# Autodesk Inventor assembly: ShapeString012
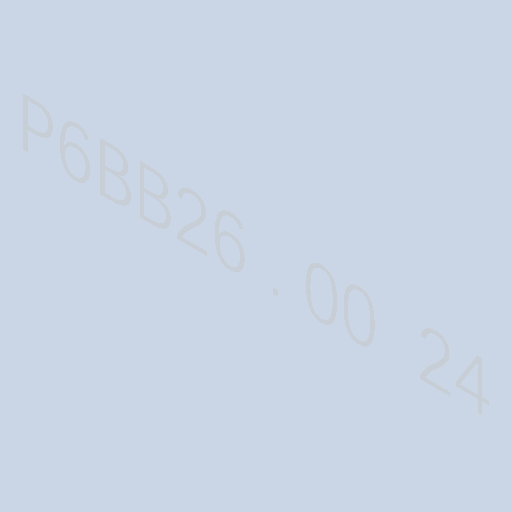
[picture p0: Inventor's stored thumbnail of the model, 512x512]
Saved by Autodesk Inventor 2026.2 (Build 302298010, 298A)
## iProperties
Created: 2026-10
Part Number: ShapeString012
Document SubType Name: Assembly
Designer: mel
Author: mel
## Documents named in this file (12)
- D:\travail\année 2026-2027\1 sti2d IT\poubelle à verre\raspberry-pico-2-microcontroller-rp2350-1.snapshot.5\raspberry_pico_2\raspberry_pico_2\ShapeString012.iam
- D:\travail\année 2026-2027\1 sti2d IT\poubelle à verre\raspberry-pico-2-microcontroller-rp2350-1.snapshot.5\raspberry_pico_2\raspberry_pico_2\ShapeString001.ipt
- D:\travail\année 2026-2027\1 sti2d IT\poubelle à verre\raspberry-pico-2-microcontroller-rp2350-1.snapshot.5\raspberry_pico_2\raspberry_pico_2\ShapeString002.ipt
- D:\travail\année 2026-2027\1 sti2d IT\poubelle à verre\raspberry-pico-2-microcontroller-rp2350-1.snapshot.5\raspberry_pico_2\raspberry_pico_2\ShapeString003.ipt
- D:\travail\année 2026-2027\1 sti2d IT\poubelle à verre\raspberry-pico-2-microcontroller-rp2350-1.snapshot.5\raspberry_pico_2\raspberry_pico_2\ShapeString004.ipt
- D:\travail\année 2026-2027\1 sti2d IT\poubelle à verre\raspberry-pico-2-microcontroller-rp2350-1.snapshot.5\raspberry_pico_2\raspberry_pico_2\ShapeString005.ipt
- D:\travail\année 2026-2027\1 sti2d IT\poubelle à verre\raspberry-pico-2-microcontroller-rp2350-1.snapshot.5\raspberry_pico_2\raspberry_pico_2\ShapeString006.ipt
- D:\travail\année 2026-2027\1 sti2d IT\poubelle à verre\raspberry-pico-2-microcontroller-rp2350-1.snapshot.5\raspberry_pico_2\raspberry_pico_2\ShapeString007.ipt
- D:\travail\année 2026-2027\1 sti2d IT\poubelle à verre\raspberry-pico-2-microcontroller-rp2350-1.snapshot.5\raspberry_pico_2\raspberry_pico_2\ShapeString008.ipt
- D:\travail\année 2026-2027\1 sti2d IT\poubelle à verre\raspberry-pico-2-microcontroller-rp2350-1.snapshot.5\raspberry_pico_2\raspberry_pico_2\ShapeString009.ipt
- D:\travail\année 2026-2027\1 sti2d IT\poubelle à verre\raspberry-pico-2-microcontroller-rp2350-1.snapshot.5\raspberry_pico_2\raspberry_pico_2\ShapeString010.ipt
- D:\travail\année 2026-2027\1 sti2d IT\poubelle à verre\raspberry-pico-2-microcontroller-rp2350-1.snapshot.5\raspberry_pico_2\raspberry_pico_2\ShapeString011.ipt
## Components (11 placed, 11 different names)
1. 2665
2. 2666
3. 2667
4. 2668
5. 2669
6. 2670
7. 2671
8. 2672
9. 2673
10. 2674
11. 2675
